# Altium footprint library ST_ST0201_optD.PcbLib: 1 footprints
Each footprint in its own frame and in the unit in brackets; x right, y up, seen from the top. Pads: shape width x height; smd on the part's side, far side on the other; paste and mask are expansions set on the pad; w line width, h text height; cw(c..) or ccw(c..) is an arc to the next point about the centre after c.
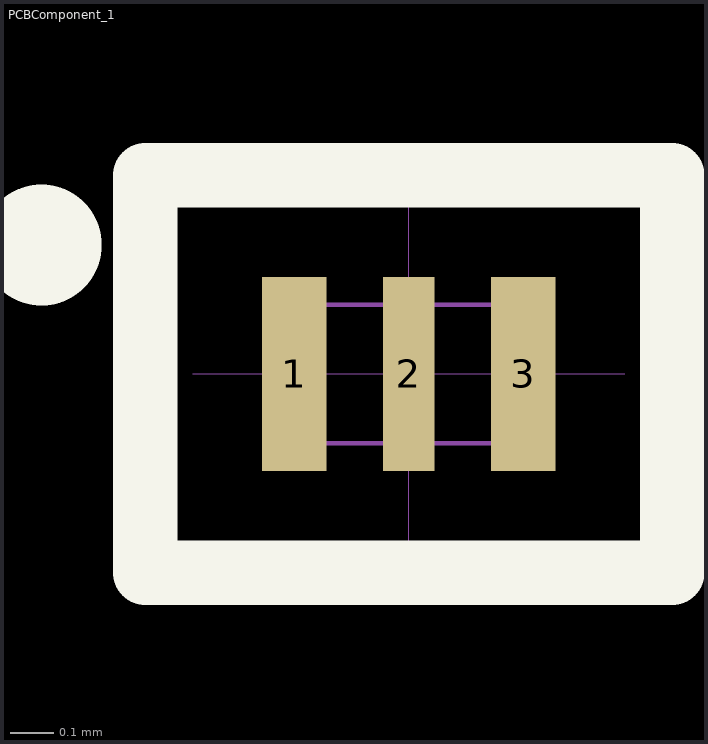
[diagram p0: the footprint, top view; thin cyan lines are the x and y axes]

## PCBComponent_1 [mm]
pads (3):
  rect 0.15x0.45 smd paste-20 mask-20: 1(-1266.871,-1267.814) 3(-1266.341,-1267.814)
  rect 0.12x0.45 smd paste-20 mask-20: 2(-1266.606,-1267.814)
Top Overlay:
  circle w0.254: c-1267.456,-1267.515 r0.013
  lines w0.15: -1267.216,-1268.274 -1267.216,-1267.354 -1265.996,-1267.354 -1265.996,-1268.274 -1267.216,-1268.274
Top Paste:
  rectangle: -1266.971,-1268.039 -1266.771,-1267.589
  rectangle: -1266.691,-1268.039 -1266.521,-1267.589
  rectangle: -1266.441,-1268.039 -1266.241,-1267.589
Top Solder:
  rectangle: -1266.431,-1268.064 -1266.251,-1267.564
  rectangle: -1266.681,-1268.064 -1266.531,-1267.564
  rectangle: -1266.961,-1268.064 -1266.781,-1267.564
Mechanical 1:
  lines w0: -1267.106,-1267.814 -1266.106,-1267.814 ; -1266.606,-1268.314 -1266.606,-1267.314
Mechanical 15:
  lines w0.01: -1266.916,-1267.974 -1266.916,-1267.654 -1266.296,-1267.654 -1266.296,-1267.974 -1266.916,-1267.974
3D body: height 0.23, standoff 0, extent -1266.916,-1267.974 -1266.296,-1267.654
